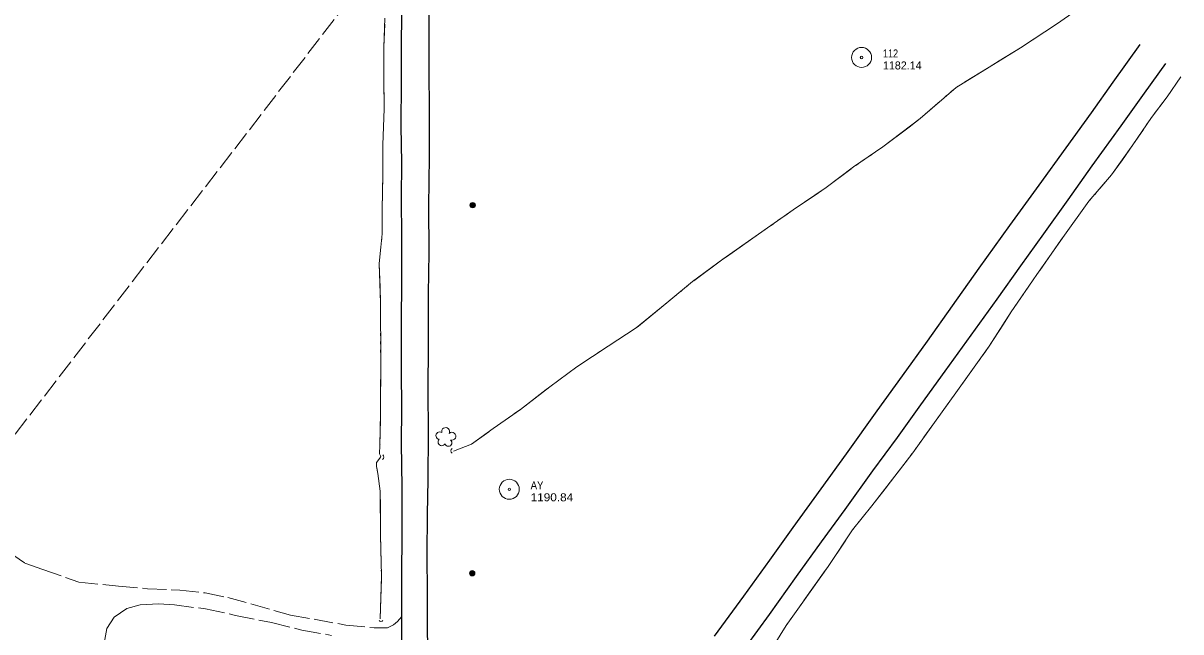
# Model space of a CAD drawing. Extents: x 299311 to 301657, y 49513 to 51866.
# Drawn here: x 300100 to 300968, y 50612 to 51068 of the extents above; entities that cross this region are included whole.
import ezdxf

# ---------------------------------------------------------------- set-up
doc = ezdxf.new("R2010")
doc.units = 0
doc.header["$LTSCALE"] = 2.4
doc.linetypes.add('LONG_DASHED', pattern=[7.5, 6, -1.5])
for name, color, linetype, lineweight in [('11', 7, 'Continuous', 25), ('14', 7, 'Continuous', 13), ('15', 7, 'Continuous', 13), ('17', 7, 'LONG_DASHED', 13), ('18', 7, 'Continuous', 13), ('19', 7, 'Continuous', 13), ('4', 7, 'Continuous', 13), ('6', 7, 'Continuous', 13)]:
    doc.layers.add(name, color=color, linetype=linetype, lineweight=lineweight)

msp = doc.modelspace()

# ---------------------------------------------------------------- linework, layer by layer
at = {"layer": '11'}
for points in [[(300403.577, 50587.789), (300403.079, 50614.351), (300402.967, 50640.73), (300402.845, 50669.714), (300403.048, 50700.357), (300403.591, 50726.031), (300403.776, 50761.043), (300403.567, 50793.454), (300403.907, 50826.683), (300403.699, 50865.411), (300404.323, 50896.349), (300404.103, 50931.122), (300404.506, 50968.277), (300404.495, 51001.599), (300404.36, 51034.274), (300404.294, 51062.123), (300404.559, 51096.335)], [(300383.961, 50584.641), (300383.895, 50619.722), (300383.761, 50651.966), (300384.018, 50687.346), (300384.101, 50720.168), (300383.499, 50753.557), (300383.697, 50779.225), (300383.489, 50807.903), (300383.501, 50844.351), (300383.694, 50874.88), (300383.739, 50907.319), (300383.592, 50937.813), (300383.69, 50963.71), (300383.399, 50991.076), (300383.456, 51024.752), (300383.606, 51055.158), (300383.946, 51088.145)], [(300618.37, 50608.824), (300640.297, 50638.797), (300659.782, 50665.83), (300677.39, 50690.39), (300698.367, 50719.356), (300717.18, 50745.629), (300740.394, 50777.658), (300759.325, 50804.001), (300778.055, 50830.114), (300796.806, 50856.474), (300816.746, 50884.609), (300839.911, 50916.666), (300861.878, 50946.903), (300882.011, 50974.899), (300900.926, 51001.273), (300917.396, 51024.192), (300937.665, 51052.35)], [(300642.077, 50601.015), (300659.645, 50625.084), (300679.903, 50653.591), (300698.643, 50679.472), (300716.287, 50703.704), (300737.124, 50732.775), (300755.534, 50757.812), (300773.071, 50782.234), (300791.205, 50807.403), (300810.794, 50834.443), (300830.21, 50861.543), (300848.154, 50886.446), (300865.265, 50910.555), (300883.514, 50935.868), (300901.661, 50961.451), (300923.277, 50991.557), (300940.807, 51015.828), (300956.806, 51038.121)]]:
    msp.add_lwpolyline(points, dxfattribs=at)
at = {"layer": '14'}
for centre, radius in [((300436.915, 50931.962), 2.018), ((300436.903, 50931.967), 1.518), ((300436.939, 50931.949), 1.008), ((300436.933, 50931.958), 0.502), ((300436.609, 50655.992), 2.018), ((300436.597, 50655.997), 1.518), ((300436.633, 50655.979), 1.008), ((300436.627, 50655.988), 0.502)]:
    msp.add_circle(centre, radius, dxfattribs=at)
at = {"layer": '15'}
for centre, radius, start, end in [((300368.154, 50743.149), 2.161, 304.40931, 50.64887), ((300422.733, 50747.737), 2.064, 125.42174, 231.66131), ((300368.171, 50621.721), 1.825, 216.7224, 322.96196)]:
    msp.add_arc(centre, radius, start, end, dxfattribs=at)
at = {"layer": '17'}
for points in [[(300076.821, 50738.367), (300077.729, 50727.23), (300079.083, 50716.341), (300077.863, 50702.938), (300076.239, 50692.819), (300078.836, 50681.762), (300088.734, 50671.932), (300101.113, 50663.594), (300114.673, 50658.749), (300141.588, 50649.285), (300171.277, 50646.24), (300192.937, 50644.404), (300217.288, 50643.397), (300236.283, 50641.204), (300253.254, 50637.828), (300300.251, 50624.664), (300341.768, 50617.194), (300363.145, 50615.021), (300373.097, 50615.103), (300377.484, 50617.292), (300380.635, 50619.728), (300383.879, 50623.635)], [(300160.542, 50603.478), (300162.516, 50614.622), (300168.007, 50623.064), (300177.457, 50629.511), (300187.488, 50632.298), (300201.242, 50632.976), (300213.373, 50632.317), (300236.659, 50629.241), (300258.94, 50624.439), (300285.941, 50619.096), (300308.719, 50613.396), (300331.014, 50609.391)]]:
    msp.add_lwpolyline(points, dxfattribs=at)
at = {"layer": '18'}
for centre, radius, start, end in [((300412.192, 50759.183), 2.777, 55.76079, 263.53379), ((300416.64, 50762.199), 2.974, 332.7899, 194.02379), ((300421.332, 50758.699), 2.975, 250.44072, 133.41399), ((300413.758, 50754.37), 2.783, 132.43781, 333.44885), ((300418.768, 50753.808), 2.611, 195.14595, 53.07856)]:
    msp.add_arc(centre, radius, start, end, dxfattribs=at)
at = {"layer": '19'}
for p, q in [((300866.246, 51062.078), (300868.002, 51063.231)), ((300871.513, 51065.537), (300873.268, 51066.689)), ((300860.979, 51058.62), (300862.735, 51059.773)), ((300800.41, 51020.827), (300802.198, 51021.929)), ((300790.799, 51012.702), (300792.383, 51014.082)), ((300795.549, 51016.841), (300797.132, 51018.22)), ((300370.438, 51000.966), (300370.514, 51003.053)), ((300948.633, 51001.171), (300949.775, 51002.689)), ((300370.209, 50994.704), (300370.285, 50996.792)), ((300942.068, 50991.843), (300943.132, 50993.42)), ((300369.98, 50988.443), (300370.056, 50990.53)), ((300734.582, 50968.784), (300736.312, 50969.975)), ((300724.203, 50961.643), (300725.933, 50962.833)), ((300729.393, 50965.214), (300731.123, 50966.404)), ((300903.505, 50940.019), (300904.748, 50941.457)), ((300896.376, 50931.127), (300897.488, 50932.671)), ((300899.778, 50935.705), (300901.02, 50937.143)), ((300369.006, 50917.452), (300369.011, 50919.541)), ((300660.749, 50916.836), (300662.467, 50918.044)), ((300665.901, 50920.46), (300667.619, 50921.668)), ((300368.487, 50904.945), (300368.679, 50907.025)), ((300368.99, 50911.188), (300368.995, 50913.276)), ((300655.597, 50913.212), (300657.315, 50914.42)), ((300862.197, 50883.053), (300878.074, 50905.62)), ((300597.796, 50871.343), (300599.411, 50872.683)), ((300855.715, 50873.656), (300856.788, 50875.227)), ((300588.101, 50863.302), (300589.716, 50864.642)), ((300592.948, 50867.322), (300594.564, 50868.662)), ((300852.496, 50868.944), (300853.569, 50870.515)), ((300367.865, 50834.016), (300367.858, 50836.105)), ((300367.888, 50827.75), (300367.881, 50829.839)), ((300367.911, 50821.484), (300367.904, 50823.573)), ((300530.645, 50821.103), (300532.398, 50822.258)), ((300520.124, 50814.17), (300521.877, 50815.326)), ((300525.384, 50817.636), (300527.138, 50818.792)), ((300813.146, 50810.592), (300814.257, 50812.138)), ((300816.478, 50815.228), (300817.589, 50816.774)), ((300809.814, 50805.956), (300810.925, 50807.502)), ((300457.556, 50768.19), (300459.277, 50769.391)), ((300462.721, 50771.793), (300464.442, 50772.994)), ((300768.784, 50748.767), (300769.889, 50750.315)), ((300772.097, 50753.412), (300773.202, 50754.96)), ((300765.406, 50744.17), (300766.556, 50745.685)), ((300365.031, 50739.388), (300366.325, 50741.026)), ((300722.04, 50688.739), (300723.227, 50690.225)), ((300725.601, 50693.197), (300726.787, 50694.683)), ((300718.842, 50684.012), (300719.901, 50685.593)), ((300368.152, 50668.736), (300368.098, 50670.822)), ((300368.312, 50662.478), (300368.258, 50664.564)), ((300368.472, 50656.22), (300368.418, 50658.306)), ((300685.282, 50635.495), (300701.275, 50657.987)), ((300367.611, 50621.784), (300368.474, 50652.047)), ((300681.977, 50630.839), (300683.079, 50632.392)), ((300675.37, 50621.527), (300676.472, 50623.079)), ((300678.674, 50626.183), (300679.775, 50627.735))]:
    msp.add_line(p, q, dxfattribs=at)
for points in [[(300422.54, 50747.544), (300436.079, 50752.836), (300452.414, 50764.604), (300472.696, 50778.751), (300494.703, 50795.792), (300515.121, 50810.874), (300538.475, 50826.262), (300559.48, 50839.875), (300584.059, 50859.95), (300601.764, 50874.634), (300624.497, 50891.449), (300651.335, 50910.214), (300677.391, 50928.542), (300702.057, 50945.115), (300722.65, 50960.575), (300744.495, 50975.604), (300772.596, 50996.84), (300799.433, 51020.225), (300824.225, 51035.504), (300847.908, 51050.037), (300874.771, 51067.676), (300889.433, 51077.924), (300902.816, 51084.623)], [(300367.611, 50621.784), (300368.529, 50653.975), (300367.751, 50684.397), (300367.645, 50717.615), (300365.811, 50730.896), (300364.854, 50736.091), (300364.807, 50739.104), (300367.267, 50742.219), (300368.148, 50743.564), (300367.067, 50745.423), (300367.421, 50751.928), (300367.748, 50775.816), (300367.931, 50816.118), (300367.775, 50858.647), (300366.916, 50887.922), (300368.988, 50910.376), (300369.035, 50928.8), (300369.486, 50955.813), (300369.566, 50977.114), (300370.559, 51004.289), (300370.308, 51025.934), (300370.418, 51050.427), (300371.169, 51072.086)], [(300370.36, 51037.506), (300370.418, 51050.427), (300371.019, 51067.773)], [(300831.702, 51040.092), (300847.908, 51050.037), (300857.468, 51056.314)], [(300370.525, 51007.229), (300370.308, 51025.934), (300370.36, 51037.506)], [(300805.773, 51024.132), (300824.225, 51035.504), (300831.702, 51040.092)], [(300657.295, 50593.107), (300672.046, 50616.841), (300684.461, 50634.34), (300703.526, 50661.153), (300721.85, 50688.501), (300736.171, 50706.432), (300753.639, 50728.658), (300767.073, 50746.367), (300783.18, 50768.952), (300799.326, 50791.364), (300824.327, 50826.148), (300840.846, 50851.888), (300859.982, 50879.904), (300880.765, 50909.445), (300899.146, 50934.974), (300916.138, 50954.637), (300932.127, 50977.095), (300945.96, 50997.616), (300957.745, 51013.289), (300968.054, 51028.172)], [(300952.059, 51005.727), (300957.745, 51013.289), (300968.054, 51028.172)], [(300764.215, 50990.506), (300772.596, 50996.84), (300787.633, 51009.943)], [(300945.258, 50996.575), (300945.96, 50997.616), (300946.348, 50998.133)], [(300739.772, 50972.355), (300744.495, 50975.604), (300764.215, 50990.506)], [(300924.233, 50966.007), (300932.127, 50977.095), (300939.942, 50988.688)], [(300369.456, 50953.993), (300369.486, 50955.813), (300369.566, 50977.114), (300369.827, 50984.268)], [(300696.233, 50941.202), (300702.057, 50945.115), (300720.798, 50959.185)], [(300907.233, 50944.332), (300916.138, 50954.637), (300924.233, 50966.007)], [(300369.022, 50923.717), (300369.035, 50928.8), (300369.456, 50953.993)], [(300671.054, 50924.084), (300677.391, 50928.542), (300696.233, 50941.202)], [(300878.074, 50905.62), (300880.765, 50909.445), (300894.153, 50928.039)], [(300627.212, 50893.347), (300651.335, 50910.214), (300652.163, 50910.796)], [(300367.425, 50870.563), (300366.916, 50887.922), (300368.103, 50900.786)], [(300602.682, 50875.313), (300624.497, 50891.449), (300627.212, 50893.347)], [(300858.934, 50878.369), (300859.982, 50879.904), (300860.007, 50879.94)], [(300367.842, 50840.282), (300367.775, 50858.647), (300367.425, 50870.563)], [(300835.048, 50842.853), (300840.846, 50851.888), (300850.35, 50865.802)], [(300561.292, 50841.355), (300584.059, 50859.95), (300584.869, 50860.622)], [(300535.905, 50824.569), (300538.475, 50826.262), (300559.48, 50839.875), (300561.292, 50841.355)], [(300819.811, 50819.864), (300824.327, 50826.148), (300835.048, 50842.853)], [(300367.799, 50787.021), (300367.931, 50816.118), (300367.927, 50817.306)], [(300492.121, 50793.793), (300494.703, 50795.792), (300515.121, 50810.874), (300516.616, 50811.859)], [(300791.479, 50780.472), (300799.326, 50791.364), (300807.593, 50802.866)], [(300467.886, 50775.396), (300472.696, 50778.751), (300492.121, 50793.793)], [(300367.487, 50756.746), (300367.748, 50775.816), (300367.799, 50787.021)], [(300775.41, 50758.057), (300783.18, 50768.952), (300791.479, 50780.472)], [(300422.54, 50747.544), (300436.079, 50752.836), (300448.985, 50762.134)], [(300452.391, 50764.587), (300452.414, 50764.604), (300454.112, 50765.789)], [(300367.343, 50750.499), (300367.421, 50751.928), (300367.43, 50752.571)], [(300367.633, 50744.45), (300367.067, 50745.423), (300367.118, 50746.368)], [(300367.684, 50705.26), (300367.645, 50717.615), (300365.811, 50730.896), (300364.998, 50735.311)], [(300746.277, 50719.291), (300753.639, 50728.658), (300763.108, 50741.141)], [(300729.161, 50697.655), (300736.171, 50706.432), (300746.277, 50719.291)], [(300367.991, 50674.994), (300367.751, 50684.397), (300367.684, 50705.26)], [(300701.275, 50657.987), (300703.526, 50661.153), (300716.723, 50680.85)], [(300658.504, 50595.052), (300672.046, 50616.841), (300673.168, 50618.423)]]:
    msp.add_lwpolyline(points, dxfattribs=at)
at = {"layer": '4', "linetype": 'LONG_DASHED'}
msp.add_line((300552.76, 51356.525), (299872.076, 50472.442), dxfattribs=at)
at = {"layer": '6'}
for centre, radius in [((300728.616, 51042.712), 7.5), ((300728.616, 51042.712), 0.96), ((300464.404, 50718.946), 7.5), ((300464.404, 50718.946), 0.96)]:
    msp.add_circle(centre, radius, dxfattribs=at)

# ---------------------------------------------------------------- texts
for s, width, p in [('112', 0.85, (300744.616, 51042.712)), ('AY', 0.9, (300480.404, 50718.946)), ('1190.84', 1.1, (300480.404, 50709.946))]:
    msp.add_text(s, height=6, dxfattribs=dict(at, width=width)).set_placement(p)
msp.add_text('1182.14', height=6, dxfattribs=at).set_placement((300744.616, 51033.712))

doc.saveas('drawing.dxf')
